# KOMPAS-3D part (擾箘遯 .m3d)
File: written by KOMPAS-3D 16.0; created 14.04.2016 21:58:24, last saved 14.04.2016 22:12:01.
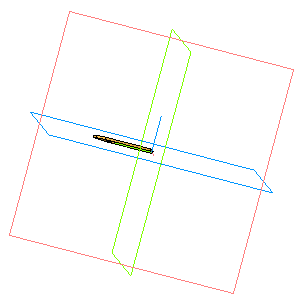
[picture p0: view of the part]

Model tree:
1. Эскиз:1
2. Операция выдавливания:1
     Расстояние 1 = 0.5; Расстояние 2 = 5; Угол 2 = 2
